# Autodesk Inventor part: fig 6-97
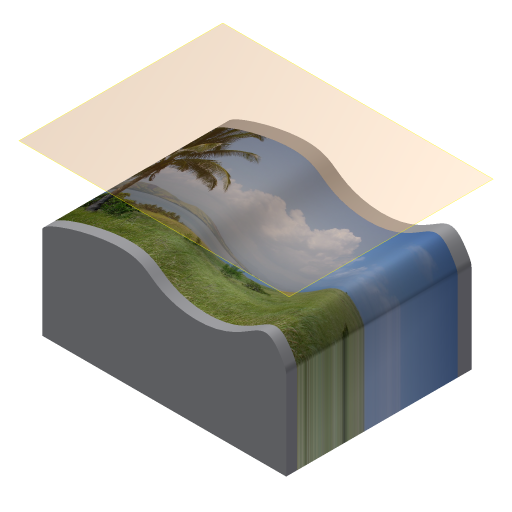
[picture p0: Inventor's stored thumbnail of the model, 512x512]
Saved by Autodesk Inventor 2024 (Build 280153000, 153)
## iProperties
Created: 2012-08
Part Number: fig 6-97
Material: Generic
Document SubType Name: Modeling
Designer: CADCIM
Density: 1 g/cm^3
Appearance: Default
Author: CADCIM
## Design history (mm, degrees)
sketch "Sketch1"
  geometry: L1 (0, 0)-(0, 12.146); L2 (32.23, 12.146)-(32.23, 0); L3 (32.23, 0)-(0, 0); 5 further points
  constraints: 6 end point, 1 parallel, 1 perpendicular, 1 vertical, 7 other
extrude "Extrusion1" new body sketch "Sketch1" distance "d0" = 24.5; taper "d1" = 0 deg
workplane "Work Plane1"
fillet "Fillet1" dims "d19" = 2
sketch "Sketch2"
  geometry: L1 (-33.343, 22.666)-(0.669, 22.666); L2 (0.669, 22.666)-(0.669, 1.409); L3 (0.669, 1.409)-(-33.343, 1.409); L4 (-33.343, 1.409)-(-33.343, 22.666); 1 other entity
  constraints: 2 other
feature "Decal1" sketch "Sketch2"
body "Solid1"
node "Image1"
other parameters: "d2" = 22
